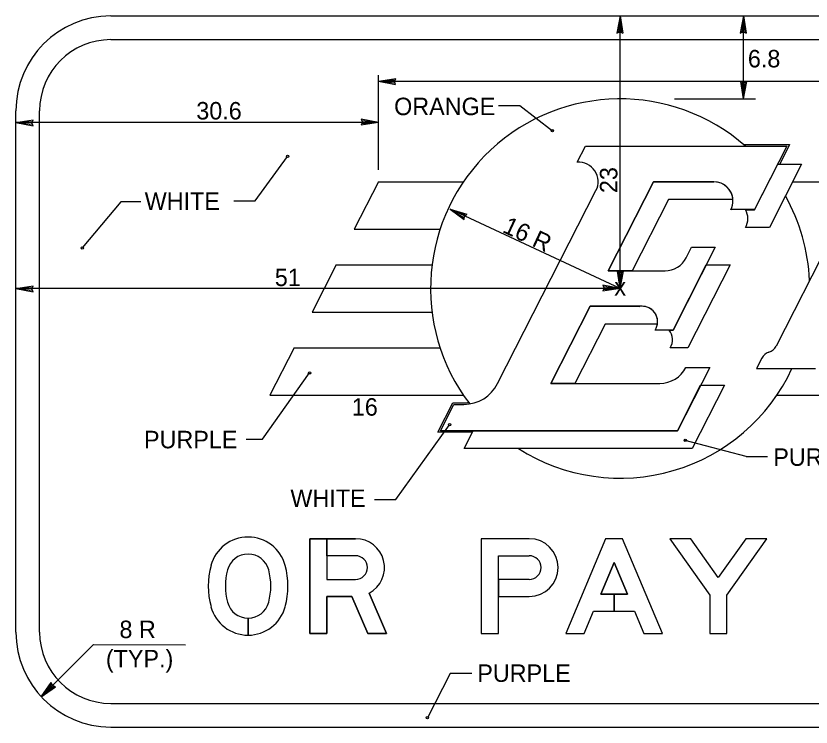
# Model space of a CAD drawing. Extents: x 319706 to 320449, y 1621775 to 1622117.
# Drawn here: x 319877.4 to 319941.2, y 1622055.9 to 1622112.9 of the extents above; entities that cross this region are included whole.
import ezdxf

# ---------------------------------------------------------------- set-up
doc = ezdxf.new("R2010")
doc.units = 0
for name, color, linetype in [('1', 7, 'Continuous'), ('52', 7, 'Continuous'), ('GSBWFill', 7, 'Continuous'), ('SignPanel', 7, 'Continuous')]:
    doc.layers.add(name, color=color, linetype=linetype)

msp = doc.modelspace()

# ---------------------------------------------------------------- linework, layer by layer
at = {"layer": '1'}
for p, q in [((319925.842, 1622091.091), (319925.842, 1622112.941)), ((319935.737, 1622106.291), (319935.737, 1622112.941)), ((319906.462, 1622100.591), (319906.462, 1622108.191)), ((319906.462, 1622107.716), (319947.578, 1622107.716)), ((319916.076, 1622105.76), (319917.795, 1622105.76)), ((319917.795, 1622105.76), (319920.416, 1622103.737)), ((319930.212, 1622106.291), (319936.688, 1622106.291)), ((319906.462, 1622104.391), (319877.392, 1622104.391)), ((319896.579, 1622098.128), (319899.177, 1622101.683)), ((319894.86, 1622098.128), (319896.579, 1622098.128)), ((319885.802, 1622098.051), (319882.707, 1622094.343)), ((319887.408, 1622098.051), (319885.802, 1622098.051)), ((319925.842, 1622091.091), (319912.201, 1622097.452)), ((319909.134, 1622091.091), (319877.392, 1622091.091)), ((319925.842, 1622091.091), (319909.134, 1622091.091)), ((319897.161, 1622079.004), (319900.935, 1622084.326)), ((319907.857, 1622074.185), (319912.167, 1622080.174)), ((319895.843, 1622079.004), (319897.161, 1622079.004)), ((319935.939, 1622077.639), (319931.06, 1622078.915)), ((319935.939, 1622077.639), (319937.659, 1622077.639)), ((319906.138, 1622074.185), (319907.857, 1622074.185)), ((319879.424, 1622058.366), (319883.612, 1622062.555)), ((319883.612, 1622062.555), (319890.998, 1622062.542)), ((319912.219, 1622060.23), (319910.392, 1622056.687)), ((319913.954, 1622060.23), (319912.219, 1622060.23))]:
    msp.add_line(p, q, dxfattribs=at)
for centre in [(319920.416, 1622103.736), (319899.177, 1622101.682), (319882.707, 1622094.343), (319900.935, 1622084.325), (319912.167, 1622080.174), (319931.06, 1622078.914), (319931.06, 1622078.914), (319910.392, 1622056.687)]:
    msp.add_circle(centre, 0.095, dxfattribs=at)
at = {"layer": '52'}
for p, q in [((319925.842, 1622112.941), (319925.574, 1622111.561)), ((319925.842, 1622112.941), (319925.703, 1622111.614)), ((319925.842, 1622112.941), (319926.062, 1622111.552)), ((319925.842, 1622112.941), (319925.935, 1622111.611)), ((319935.737, 1622112.941), (319935.469, 1622111.561)), ((319935.737, 1622112.941), (319935.598, 1622111.614)), ((319935.737, 1622112.941), (319935.957, 1622111.552)), ((319935.737, 1622112.941), (319935.83, 1622111.611)), ((319925.574, 1622111.561), (319925.82, 1622111.662)), ((319925.82, 1622111.662), (319926.062, 1622111.552)), ((319935.469, 1622111.561), (319935.715, 1622111.663)), ((319935.715, 1622111.663), (319935.957, 1622111.552)), ((319906.462, 1622107.716), (319907.851, 1622107.937)), ((319906.462, 1622107.716), (319907.792, 1622107.809)), ((319906.462, 1622107.716), (319907.842, 1622107.448)), ((319906.462, 1622107.716), (319907.789, 1622107.578)), ((319907.74, 1622107.695), (319907.851, 1622107.937)), ((319907.842, 1622107.448), (319907.74, 1622107.695)), ((319935.737, 1622106.291), (319935.516, 1622107.68)), ((319935.759, 1622107.57), (319935.516, 1622107.68)), ((319935.737, 1622106.291), (319936.005, 1622107.672)), ((319936.005, 1622107.672), (319935.759, 1622107.57)), ((319935.737, 1622106.291), (319935.644, 1622107.621)), ((319935.737, 1622106.291), (319935.876, 1622107.618)), ((319877.392, 1622104.391), (319878.781, 1622104.612)), ((319877.392, 1622104.391), (319878.722, 1622104.484)), ((319878.67, 1622104.37), (319878.781, 1622104.612)), ((319906.462, 1622104.391), (319905.081, 1622104.659)), ((319905.081, 1622104.659), (319905.183, 1622104.413)), ((319906.462, 1622104.391), (319905.134, 1622104.53)), ((319877.392, 1622104.391), (319878.772, 1622104.123)), ((319877.392, 1622104.391), (319878.719, 1622104.253)), ((319878.772, 1622104.123), (319878.67, 1622104.37)), ((319905.183, 1622104.413), (319905.073, 1622104.171)), ((319906.462, 1622104.391), (319905.073, 1622104.171)), ((319906.462, 1622104.391), (319905.132, 1622104.298)), ((319912.201, 1622097.452), (319913.552, 1622097.064)), ((319912.201, 1622097.452), (319913.339, 1622096.626)), ((319912.201, 1622097.452), (319913.344, 1622096.765)), ((319912.201, 1622097.452), (319913.445, 1622096.974)), ((319913.339, 1622096.626), (319913.35, 1622096.892)), ((319913.35, 1622096.892), (319913.552, 1622097.064)), ((319925.842, 1622091.091), (319925.621, 1622092.48)), ((319925.863, 1622092.37), (319925.621, 1622092.48)), ((319925.842, 1622091.091), (319925.749, 1622092.421)), ((319925.842, 1622091.091), (319926.11, 1622092.471)), ((319925.842, 1622091.091), (319925.98, 1622092.418)), ((319926.11, 1622092.471), (319925.863, 1622092.37)), ((319877.392, 1622091.091), (319878.781, 1622091.311)), ((319877.392, 1622091.091), (319878.722, 1622091.184)), ((319877.392, 1622091.091), (319878.772, 1622090.823)), ((319877.392, 1622091.091), (319878.719, 1622090.952)), ((319878.67, 1622091.069), (319878.781, 1622091.311)), ((319878.772, 1622090.823), (319878.67, 1622091.069)), ((319924.563, 1622091.113), (319924.453, 1622090.87)), ((319925.842, 1622091.091), (319924.453, 1622090.87)), ((319925.842, 1622091.091), (319924.461, 1622091.359)), ((319924.461, 1622091.359), (319924.563, 1622091.113)), ((319925.842, 1622091.091), (319924.512, 1622090.998)), ((319925.842, 1622091.091), (319924.514, 1622091.23)), ((319879.424, 1622058.366), (319880.23, 1622059.518)), ((319879.424, 1622058.366), (319880.281, 1622059.388)), ((319879.424, 1622058.366), (319880.446, 1622059.224)), ((319880.328, 1622059.271), (319880.23, 1622059.518)), ((319880.575, 1622059.172), (319880.328, 1622059.271)), ((319879.424, 1622058.366), (319880.575, 1622059.172))]:
    msp.add_line(p, q, dxfattribs=at)
at = {"layer": 'GSBWFill'}
for p, q in [((319916.08, 1622069.672), (319918.55, 1622069.672)), ((319916.08, 1622069.672), (319918.55, 1622069.672)), ((319916.08, 1622069.672), (319918.55, 1622069.672)), ((319916.08, 1622066.403), (319918.55, 1622066.403)), ((319896.011, 1622064.674), (319896.011, 1622063.306)), ((319896.011, 1622064.674), (319896.011, 1622063.306)), ((319896.012, 1622063.306), (319896.012, 1622064.674)), ((319896.012, 1622063.306), (319896.012, 1622064.674))]:
    msp.add_line(p, q, dxfattribs=at)
for points in [[(319904.627, 1622071.041), (319900.952, 1622071.041), (319900.952, 1622063.439), (319902.321, 1622063.439), (319902.321, 1622066.403), (319904.335, 1622066.403), (319905.619, 1622063.439), (319907.11, 1622063.439), (319905.71, 1622066.672)], [(319905.71, 1622066.672), (319907.11, 1622063.439), (319905.619, 1622063.439), (319904.335, 1622066.403), (319902.321, 1622066.403), (319902.321, 1622063.439), (319900.952, 1622063.439), (319900.952, 1622071.041), (319902.32, 1622071.041), (319902.321, 1622067.772), (319904.627, 1622067.772)], [(319905.71, 1622066.672), (319907.11, 1622063.439), (319905.619, 1622063.439), (319904.335, 1622066.403), (319902.321, 1622066.403), (319902.321, 1622063.439), (319900.952, 1622063.439), (319900.952, 1622071.041), (319902.32, 1622071.041), (319902.321, 1622067.772), (319904.627, 1622067.772)], [(319902.321, 1622069.672), (319902.321, 1622071.041), (319904.627, 1622071.041)], [(319902.321, 1622069.672), (319902.321, 1622071.041), (319904.627, 1622071.041)], [(319918.55, 1622071.041), (319914.712, 1622071.041), (319914.712, 1622063.439), (319916.08, 1622063.439), (319916.08, 1622066.403)], [(319918.55, 1622071.041), (319914.712, 1622071.041), (319914.712, 1622063.439), (319916.08, 1622063.439), (319916.08, 1622069.672)], [(319918.55, 1622071.041), (319914.712, 1622071.041), (319914.712, 1622063.439), (319916.08, 1622063.439), (319916.08, 1622069.672)], [(319904.627, 1622069.672), (319902.321, 1622069.672), (319902.321, 1622067.772), (319904.627, 1622067.772)], [(319904.627, 1622069.672), (319902.321, 1622069.672)], [(319904.627, 1622069.672), (319902.321, 1622069.672)], [(319918.55, 1622067.772), (319916.08, 1622067.772), (319916.08, 1622069.672)], [(319918.55, 1622067.772), (319916.08, 1622067.772), (319916.08, 1622066.403), (319918.55, 1622066.403)], [(319918.55, 1622067.772), (319916.08, 1622067.772), (319916.08, 1622066.403), (319918.55, 1622066.403)]]:
    msp.add_lwpolyline(points, dxfattribs=at)
for points in [[(319923.712, 1622065.225), (319926.997, 1622065.225), (319927.747, 1622063.439), (319929.231, 1622063.439), (319926.038, 1622071.041), (319924.67, 1622071.041), (319921.477, 1622063.439), (319922.961, 1622063.439)], [(319926.422, 1622066.594), (319925.354, 1622066.594), (319925.354, 1622065.225), (319926.997, 1622065.225), (319927.747, 1622063.439), (319929.231, 1622063.439), (319926.038, 1622071.041), (319924.67, 1622071.041), (319921.477, 1622063.439), (319922.961, 1622063.439), (319923.712, 1622065.225), (319925.354, 1622065.225), (319925.354, 1622066.594), (319924.286, 1622066.594), (319925.354, 1622069.136)], [(319926.422, 1622066.594), (319925.354, 1622066.594), (319925.354, 1622065.225), (319926.997, 1622065.225), (319927.747, 1622063.439), (319929.231, 1622063.439), (319926.038, 1622071.041), (319924.67, 1622071.041), (319921.477, 1622063.439), (319922.961, 1622063.439), (319923.712, 1622065.225), (319925.354, 1622065.225), (319925.354, 1622066.594), (319924.286, 1622066.594), (319925.354, 1622069.136)], [(319934.4, 1622066.518), (319937.593, 1622071.041), (319935.918, 1622071.041), (319933.716, 1622067.921), (319931.514, 1622071.041), (319929.839, 1622071.041), (319933.032, 1622066.518), (319933.032, 1622063.439), (319934.4, 1622063.439)], [(319934.4, 1622066.518), (319937.593, 1622071.041), (319935.918, 1622071.041), (319933.716, 1622067.921), (319931.514, 1622071.041), (319929.839, 1622071.041), (319933.032, 1622066.518), (319933.032, 1622063.439), (319934.4, 1622063.439)], [(319934.4, 1622066.518), (319937.593, 1622071.041), (319935.918, 1622071.041), (319933.716, 1622067.921), (319931.514, 1622071.041), (319929.839, 1622071.041), (319933.032, 1622066.518), (319933.032, 1622063.439), (319934.4, 1622063.439)], [(319926.422, 1622066.594), (319925.354, 1622069.136), (319924.286, 1622066.594)]]:
    msp.add_lwpolyline(points, close=True, dxfattribs=at)
for centre, radius, start, end in [((319896.011, 1622068.093), 3.081, 14.96177, 165.03823), ((319896.011, 1622068.093), 3.081, 14.96177, 165.03823), ((319896.011, 1622068.093), 3.081, 14.96177, 165.03823), ((319904.627, 1622068.722), 2.319, 297.837, 90), ((319904.627, 1622068.722), 2.319, 297.837, 90), ((319904.627, 1622068.722), 2.319, 297.837, 90), ((319896.011, 1622068.093), 1.712, 14.96177, 165.03823), ((319896.011, 1622068.093), 1.712, 14.96177, 165.03823), ((319896.011, 1622068.093), 1.712, 14.96177, 165.03823), ((319904.627, 1622068.722), 0.95, 270, 90), ((319904.627, 1622068.722), 0.95, 270, 90), ((319904.627, 1622068.722), 0.95, 270, 90), ((319899.204, 1622067.24), 6.385, 165.03823, 194.96177), ((319899.204, 1622067.24), 6.385, 165.03823, 194.96177), ((319899.204, 1622067.24), 6.385, 165.03823, 194.96177), ((319892.818, 1622067.24), 6.385, 345.03823, 14.96177), ((319892.818, 1622067.24), 6.385, 345.03823, 14.96177), ((319892.818, 1622067.24), 6.385, 345.03823, 14.96177), ((319899.204, 1622067.24), 5.017, 165.03823, 194.96177), ((319899.204, 1622067.24), 5.017, 165.03823, 194.96177), ((319899.204, 1622067.24), 5.017, 165.03823, 194.96177), ((319892.818, 1622067.24), 5.017, 345.03823, 14.96177), ((319892.818, 1622067.24), 5.017, 345.03823, 14.96177), ((319892.818, 1622067.24), 5.017, 345.03823, 14.96177), ((319896.011, 1622066.386), 3.081, 194.96177, 345.03823), ((319896.011, 1622066.386), 3.081, 194.96177, 270), ((319896.011, 1622066.386), 3.081, 194.96177, 270), ((319896.011, 1622066.386), 1.712, 194.96177, 345.03823), ((319896.011, 1622066.386), 1.712, 194.96177, 270), ((319896.011, 1622066.386), 1.712, 194.96177, 270), ((319896.011, 1622066.386), 1.712, 270.01272, 345.03823), ((319896.011, 1622066.386), 1.712, 270.01272, 345.03823), ((319896.011, 1622066.386), 3.081, 270.00707, 345.03823), ((319896.011, 1622066.386), 3.081, 270.00707, 345.03823)]:
    msp.add_arc(centre, radius, start, end, dxfattribs=at)
for major_axis in [(0, 2.319), (0, 2.319), (0, 2.319), (0, 0.95), (0, 0.95), (0, 0.95)]:
    msp.add_ellipse((319918.55, 1622068.722), major_axis=major_axis, ratio=0.999994, start_param=3.141593, end_param=6.283185, dxfattribs=at)
at = {"layer": 'SignPanel'}
for p, q in [((319884.992, 1622112.941), (320006.593, 1622112.941)), ((319884.992, 1622111.041), (320006.593, 1622111.041)), ((319877.392, 1622063.541), (319877.392, 1622105.341)), ((319879.292, 1622063.541), (319879.292, 1622105.341)), ((319935.731, 1622102.633), (319939.435, 1622102.633)), ((319939.435, 1622102.633), (319938.636, 1622101.066)), ((319922.404, 1622101.216), (319923.052, 1622102.491)), ((319923.052, 1622102.491), (319939.202, 1622102.491)), ((319939.202, 1622102.491), (319936.616, 1622097.412)), ((319936.612, 1622097.406), (319938.478, 1622101.066)), ((319936.612, 1622097.406), (319938.478, 1622101.066)), ((319940.397, 1622101.066), (319937.808, 1622095.986)), ((319940.397, 1622101.066), (319937.808, 1622095.986)), ((319938.478, 1622101.066), (319940.397, 1622101.066)), ((319938.478, 1622101.066), (319940.397, 1622101.066)), ((319906.462, 1622099.641), (319904.528, 1622095.841)), ((319906.462, 1622099.641), (319913.274, 1622099.641)), ((319928.526, 1622099.641), (319924.896, 1622092.516)), ((319924.896, 1622092.516), (319928.526, 1622099.641)), ((319924.896, 1622092.516), (319928.526, 1622099.641)), ((319933.368, 1622099.641), (319928.526, 1622099.641)), ((319928.526, 1622099.641), (319933.368, 1622099.641)), ((319928.526, 1622099.641), (319933.368, 1622099.641)), ((319939.669, 1622099.641), (319993.863, 1622099.641)), ((319916.021, 1622083.466), (319923.906, 1622098.942)), ((319929.719, 1622098.216), (319926.814, 1622092.516)), ((319929.719, 1622098.216), (319926.814, 1622092.516)), ((319934.887, 1622098.216), (319929.719, 1622098.216)), ((319934.887, 1622098.216), (319929.719, 1622098.216)), ((319936.616, 1622097.412), (319934.714, 1622097.412)), ((319935.906, 1622097.406), (319936.612, 1622097.406)), ((319935.906, 1622097.406), (319936.612, 1622097.406)), ((319904.528, 1622095.841), (319911.403, 1622095.841)), ((319937.808, 1622095.986), (319935.908, 1622095.986)), ((319937.808, 1622095.986), (319935.908, 1622095.986)), ((319943.053, 1622095.707), (319938.349, 1622086.476)), ((319933.473, 1622094.416), (319930.086, 1622087.766)), ((319931.133, 1622093.553), (319931.573, 1622094.416)), ((319931.573, 1622094.416), (319933.473, 1622094.416)), ((319903.078, 1622092.991), (319901.143, 1622089.191)), ((319903.078, 1622092.991), (319910.76, 1622092.991)), ((319930.086, 1622087.766), (319932.748, 1622092.991)), ((319930.086, 1622087.766), (319932.748, 1622092.991)), ((319934.667, 1622092.991), (319931.278, 1622086.341)), ((319934.667, 1622092.991), (319931.278, 1622086.341)), ((319932.748, 1622092.991), (319934.667, 1622092.991)), ((319932.748, 1622092.991), (319934.667, 1622092.991)), ((319924.896, 1622092.516), (319929.441, 1622092.516)), ((319926.814, 1622092.516), (319924.896, 1622092.516)), ((319926.814, 1622092.516), (319924.896, 1622092.516)), ((319901.143, 1622089.191), (319910.76, 1622089.191)), ((319923.444, 1622089.666), (319920.298, 1622083.491)), ((319920.298, 1622083.491), (319923.444, 1622089.666)), ((319920.298, 1622083.491), (319923.444, 1622089.666)), ((319927.613, 1622089.666), (319923.444, 1622089.666)), ((319923.444, 1622089.666), (319927.434, 1622089.653)), ((319923.444, 1622089.666), (319927.434, 1622089.653)), ((319924.636, 1622088.237), (319922.217, 1622083.491)), ((319924.636, 1622088.237), (319922.217, 1622083.491)), ((319928.83, 1622088.224), (319924.636, 1622088.237)), ((319928.83, 1622088.224), (319924.636, 1622088.237)), ((319930.086, 1622087.766), (319928.654, 1622087.766)), ((319929.787, 1622087.766), (319930.086, 1622087.766)), ((319929.787, 1622087.766), (319930.086, 1622087.766)), ((319899.692, 1622086.341), (319897.758, 1622082.541)), ((319899.692, 1622086.341), (319911.403, 1622086.341)), ((319931.278, 1622086.341), (319929.853, 1622086.341)), ((319931.278, 1622086.341), (319929.853, 1622086.341)), ((319937.194, 1622085.516), (319936.768, 1622084.677)), ((319933.024, 1622084.77), (319930.437, 1622079.691)), ((319931.123, 1622084.77), (319933.024, 1622084.77)), ((319936.768, 1622084.677), (319941.518, 1622084.677)), ((319920.298, 1622083.491), (319929.017, 1622083.491)), ((319922.217, 1622083.491), (319920.298, 1622083.491)), ((319922.217, 1622083.491), (319920.298, 1622083.491)), ((319930.437, 1622079.691), (319932.298, 1622083.345)), ((319930.437, 1622079.691), (319932.298, 1622083.345)), ((319934.218, 1622083.345), (319931.629, 1622078.266)), ((319934.218, 1622083.345), (319931.629, 1622078.266)), ((319932.298, 1622083.345), (319934.218, 1622083.345)), ((319932.298, 1622083.345), (319934.218, 1622083.345)), ((319897.758, 1622082.541), (319913.274, 1622082.541)), ((319938.409, 1622082.541), (319985.149, 1622082.541)), ((319911.233, 1622079.566), (319912.438, 1622081.931)), ((319911.437, 1622079.691), (319912.514, 1622081.806)), ((319912.438, 1622081.931), (319913.312, 1622081.931)), ((319912.514, 1622081.806), (319913.312, 1622081.806)), ((319930.437, 1622079.691), (319911.437, 1622079.691)), ((319913.337, 1622078.266), (319914.062, 1622079.691)), ((319913.337, 1622078.266), (319914.062, 1622079.691)), ((319914.062, 1622079.691), (319930.437, 1622079.691)), ((319914.062, 1622079.691), (319930.437, 1622079.691)), ((319913.999, 1622079.566), (319911.233, 1622079.566)), ((319931.629, 1622078.266), (319913.337, 1622078.266)), ((319931.629, 1622078.266), (319913.337, 1622078.266)), ((319884.992, 1622057.841), (320006.593, 1622057.841)), ((319884.992, 1622055.941), (320006.593, 1622055.941))]:
    msp.add_line(p, q, dxfattribs=at)
for centre, radius, start, end in [((319884.991, 1622105.339), 7.6, 90, 180), ((319884.991, 1622105.339), 5.7, 90, 180), ((319925.842, 1622091.089), 15.2, 48.59038, 217.4727), ((319922.508, 1622099.652), 1.568, 332.99985, 93.80449), ((319933.369, 1622098.119), 1.52, 332.20885, 90), ((319933.369, 1622098.119), 1.52, 3.58332, 90), ((319933.369, 1622098.119), 1.52, 3.58332, 90), ((319925.842, 1622091.089), 15.2, 2.42356, 29.27706), ((319934.562, 1622096.694), 1.52, 332.20885, 27.91266), ((319934.562, 1622096.694), 1.52, 332.20885, 27.91266), ((319929.441, 1622094.414), 1.9, 270, 332.98829), ((319927.613, 1622088.429), 1.235, 350.35016, 98.33436), ((319927.613, 1622088.429), 1.235, 350.35016, 98.33436), ((319927.613, 1622088.429), 1.235, 327.42103, 90), ((319928.813, 1622087.004), 1.235, 327.42103, 37.97987), ((319928.813, 1622087.004), 1.235, 327.42103, 37.97987), ((319938.04, 1622085.083), 0.95, 106.43168, 152.97425), ((319937.503, 1622086.906), 0.95, 286.43167, 332.99588), ((319929.016, 1622085.864), 2.375, 270, 332.5096), ((319925.842, 1622091.089), 15.2, 237.53826, 335.04698), ((319913.312, 1622084.846), 3.04, 270, 332.99913), ((319913.312, 1622084.846), 2.917, 270, 277.50379), ((319884.991, 1622063.539), 7.6, 180, 270), ((319884.991, 1622063.539), 5.7, 180, 270)]:
    msp.add_arc(centre, radius, start, end, dxfattribs=at)

# ---------------------------------------------------------------- texts
at = {"layer": '1'}
for s, p in [('6.8', (319936.086, 1622108.815)), ('ORANGE', (319907.719, 1622104.987)), ('30.6', (319891.855, 1622104.64)), ('WHITE', (319887.718, 1622097.396)), ('51', (319898.153, 1622091.287)), ('x', (319925.378, 1622090.53)), ('16', (319904.327, 1622080.899)), ('PURPLE', (319887.663, 1622078.285)), ('PURPLE', (319938.122, 1622076.879)), ('WHITE', (319899.403, 1622073.582)), ('PURPLE', (319914.387, 1622059.561))]:
    msp.add_text(s, height=1.4, dxfattribs=at).set_placement(p)
for s, rotation, p in [('23', 90, (319925.619, 1622098.74)), ('16 R', 334.99906, (319916.331, 1622095.641)), ('8 R', 0.16499, (319885.697, 1622063.07)), ('(TYP.)', 0.16499, (319884.608, 1622060.717))]:
    msp.add_text(s, height=1.4, rotation=rotation, dxfattribs=at).set_placement(p)

doc.saveas('drawing.dxf')
